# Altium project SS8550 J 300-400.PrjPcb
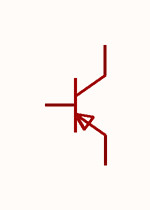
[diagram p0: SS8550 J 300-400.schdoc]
1 sheet, 1 parts. Net scope: global (net labels, ports and power ports of the same name join across sheets).

## Sheet SS8550 J 300-400.schdoc
size 127 x 101 mm

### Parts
Q?  ss8550(range:300-400)  [SOT-23-3_L2.9-W1.6-P1.90-LS2.8-BR]  (value not drawn)

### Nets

Not connected (* = marked no-connect by the designer): Q? 1(B) 2(E) 3(C)

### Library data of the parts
Q? = ss8550(range:300-400): 晶体管类型:PNP;集电极电流(Ic):1.5A;集射极击穿电压(Vceo):25V;耗散功率(Pd):300mW;直流电流增益(hFE):300;; Manufacturer: CJ(江苏长电/长晶); Symbol: SS8550 J 300-400; AddInBom: yes; ModelId: 89cb27a44ab2466697082bb9fd73a7d0; ModelName: SOT-23-3L_L2.9-W1.6-H1.1-LS2.8-P0.95; ModelTransform: 114.173,110.236,0,90,0,0,0,0,0; type: PNP; Current - Collector(Ic): 1.5A; Collector - Emitter Voltage VCEO: 25V; Pd - Power Dissipation: 300mW; DC Current Gain: 300; Transition frequency(fT): 100MHz; Current - Collector Cutoff: 100nA; Vce Saturation(VCE(sat)): 500mV; Emitter-Base Voltage(Vebo): 5V; Number: 1个PNP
